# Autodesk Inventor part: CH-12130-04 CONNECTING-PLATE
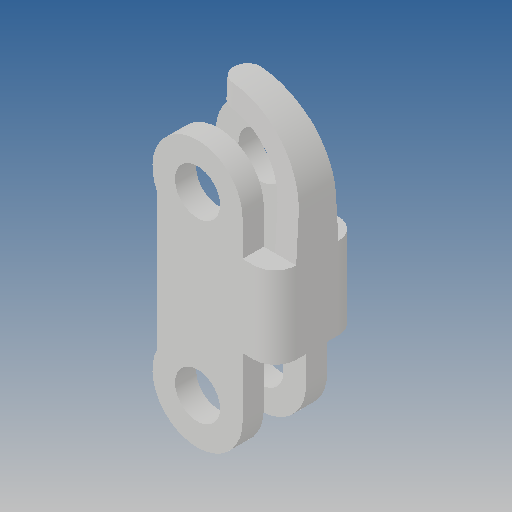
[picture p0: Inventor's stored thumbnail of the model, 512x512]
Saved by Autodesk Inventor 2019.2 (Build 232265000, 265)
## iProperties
Created: 2012-09
Part Number: CH-12130-04 CONNECTING-PLATE
Material: Ogólny
Document SubType Name: Modeling
Designer: CADENGINEERING4
Density: 1 g/cm^3
Appearance: Domyślna
Author: CADENGINEERING4
Revision Number: ÈÎºÎ
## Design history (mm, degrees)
feature "Ô²½Ç2"
feature "ÇÐ³ý-À­Éì3"
node "Bryła1"
node "Bryła2"
